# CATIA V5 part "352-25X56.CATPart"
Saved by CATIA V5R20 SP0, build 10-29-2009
Part number: 352-25X56
Definition: NONE
Nomenclature: 352-25X56
Source: Unknown
Description: 352-25X56
Bounding box of the stored display mesh (mm): x 0 to 56, y -17 to 17, z -17 to 17
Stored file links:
  C:\Users\Utente\Desktop\IO LAVORO\3D X SITO CF\X SITO\PLASTICA\352\352-25X56.CATPart

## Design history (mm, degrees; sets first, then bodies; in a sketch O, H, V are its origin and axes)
Body1 "352-25X56" (main body)
  Solid1: solid without history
